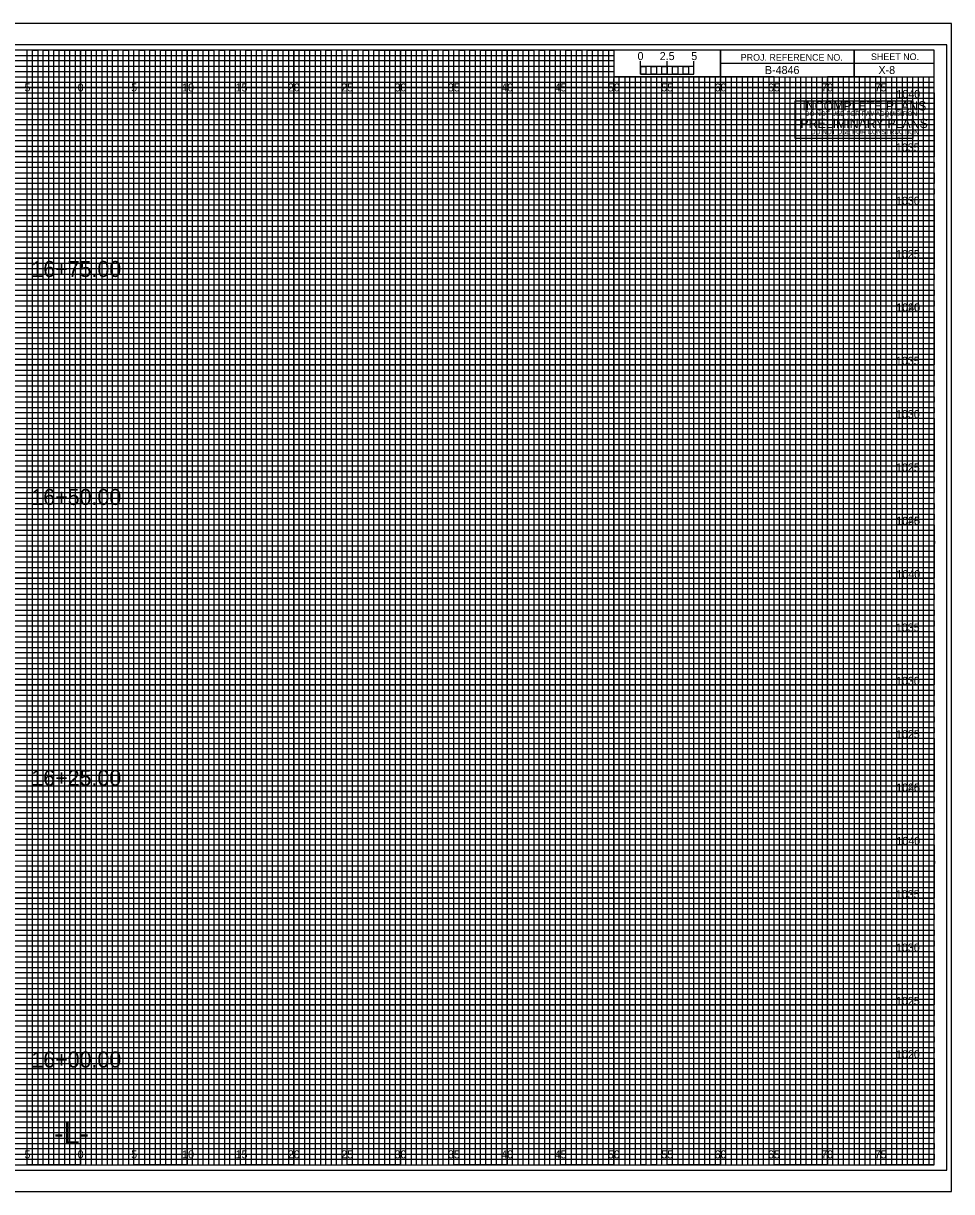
# Model space of a CAD drawing. Extents: x -7 to 162, y -2 to 987.
# Drawn here: x 74.6 to 161.7, y 767.5 to 877 of the extents above; entities that cross this region are included whole.
import ezdxf

# ---------------------------------------------------------------- set-up
doc = ezdxf.new("R2010")
doc.units = 0
for name, color, linetype in [('Default', 7, 'Continuous'), ('Exist Cross Section Cell', 7, 'Continuous'), ('Exist XS Center Line Elevation Label', 7, 'Continuous'), ('Exist XS Ground Line', 7, 'Continuous'), ('Prop CMT Concrete Structures', 7, 'Continuous'), ('Prop CMT DNC', 7, 'Continuous'), ('Prop CMT Guardrail Graphics', 7, 'Continuous'), ('Prop CMT Guardrail Widen Shoulder', 7, 'Continuous'), ('Prop CMT Pvmt Course 1', 7, 'Continuous'), ('Prop CMT Pvmt Surface', 7, 'Continuous'), ('Prop CMT Pvmt Surface Shoulder', 7, 'Continuous'), ('Prop CMT Shld Paved Course 1', 7, 'Continuous'), ('Prop CMT Shoulder Point', 7, 'Continuous'), ('Prop CMT Slope Grass', 7, 'Continuous'), ('Prop CMT Subgrade Earthwork', 7, 'Continuous'), ('Prop XS SE Text', 7, 'Continuous'), ('Prop XS Side Slope Text', 7, 'Continuous'), ('Typical Text Label CELL', 7, 'Continuous')]:
    doc.layers.add(name, color=color, linetype=linetype)

msp = doc.modelspace()

# ---------------------------------------------------------------- linework, layer by layer
at = {"layer": 'Default'}
for points in [[(146.99, 867.97), (146.99, 869.73), (158.01, 869.73), (158.01, 867.97)], [(146.99, 866.2), (146.99, 867.97), (158.01, 867.97), (158.01, 866.2)]]:
    msp.add_lwpolyline(points, close=True, dxfattribs=at)
at = {"layer": 'Exist XS Center Line Elevation Label'}
for points in [[(72.5, 770), (77.5, 770), (77.5, 874.5), (82.5, 874.5), (82.5, 770), (87.5, 770), (87.5, 874.5), (92.5, 874.5), (92.5, 770), (97.5, 770), (97.5, 874.5), (102.5, 874.5), (102.5, 770), (107.5, 770), (107.5, 874.5), (112.5, 874.5), (112.5, 770), (117.5, 770), (117.5, 874.5), (122.5, 874.5), (122.5, 770), (127.5, 770), (127.5, 874.5), (129.97, 874.5), (130, 874.5), (130, 872), (132.5, 872), (132.5, 770), (137.5, 770), (137.5, 872), (142.5, 872), (142.5, 770), (147.5, 770), (147.5, 872), (152.5, 872), (152.5, 770), (157.5, 770), (157.5, 872)], [(0, 872), (137.5, 872)], [(0, 862.5), (160, 862.5), (160, 867.5), (0, 867.5)], [(0, 852.5), (160, 852.5), (160, 857.5), (0, 857.5)], [(0, 842.5), (160, 842.5), (160, 847.5), (0, 847.5)], [(0, 832.5), (160, 832.5), (160, 837.5), (0, 837.5)], [(0, 822.5), (160, 822.5), (160, 827.5), (0, 827.5)], [(0, 812.5), (160, 812.5), (160, 817.5), (0, 817.5)], [(0, 802.5), (160, 802.5), (160, 807.5), (0, 807.5)], [(0, 792.5), (160, 792.5), (160, 797.5), (0, 797.5)], [(0, 782.5), (160, 782.5), (160, 787.5), (0, 787.5)], [(0, 772.5), (160, 772.5), (160, 777.5), (0, 777.5)]]:
    msp.add_lwpolyline(points, dxfattribs=at)
at = {"layer": 'Exist XS Ground Line'}
for p, q in [((75, 874.5), (70, 874.5)), ((75, 770), (75, 874.5)), ((85, 874.5), (80, 874.5)), ((80, 874.5), (80, 770)), ((85, 770), (85, 874.5)), ((95, 874.5), (90, 874.5)), ((90, 874.5), (90, 770)), ((95, 770), (95, 874.5)), ((105, 874.5), (100, 874.5)), ((100, 874.5), (100, 770)), ((105, 770), (105, 874.5)), ((115, 874.5), (110, 874.5)), ((110, 874.5), (110, 770)), ((115, 770), (115, 874.5)), ((125, 874.5), (120, 874.5)), ((120, 874.5), (120, 770)), ((125, 770), (125, 874.5)), ((130, 874.5), (130, 770)), ((135, 770), (135, 872)), ((145, 872), (140, 872)), ((140, 872), (140, 770)), ((145, 770), (145, 872)), ((155, 872), (150, 872)), ((150, 872), (150, 770)), ((155, 770), (155, 872)), ((80, 770), (75, 770)), ((90, 770), (85, 770)), ((100, 770), (95, 770)), ((110, 770), (105, 770)), ((120, 770), (115, 770)), ((130, 770), (125, 770)), ((140, 770), (135, 770)), ((150, 770), (145, 770)), ((160, 770), (155, 770)), ((160, 770), (160, 770))]:
    msp.add_line(p, q, dxfattribs=at)
for points in [[(0, 870), (160, 870), (160, 865), (0, 865)], [(0, 860), (160, 860), (160, 855), (0, 855)], [(0, 850), (160, 850), (160, 845), (0, 845)], [(0, 840), (160, 840), (160, 835), (0, 835)], [(0, 830), (160, 830), (160, 825), (0, 825)], [(0, 820), (160, 820), (160, 815), (0, 815)], [(0, 810), (160, 810), (160, 805), (0, 805)], [(0, 800), (160, 800), (160, 795), (0, 795)], [(0, 790), (160, 790), (160, 785), (0, 785)], [(0, 780), (160, 780), (160, 775), (0, 775)]]:
    msp.add_lwpolyline(points, dxfattribs=at)
at = {"layer": 'Prop CMT Concrete Structures'}
for p, q in [((75, 770), (75, 874.5)), ((80, 770), (80, 874.5)), ((85, 770), (85, 874.5)), ((90, 770), (90, 874.5)), ((95, 770), (95, 874.5)), ((100, 770), (100, 874.5)), ((105, 770), (105, 874.5)), ((110, 770), (110, 874.5)), ((115, 770), (115, 874.5)), ((120, 770), (120, 874.5)), ((125, 770), (125, 874.5)), ((130, 770), (130, 871.84)), ((135, 770), (135, 871.84)), ((140, 770), (140, 871.84)), ((145, 770), (145, 871.84)), ((150, 770), (150, 871.84)), ((155, 770), (155, 871.84)), ((0, 870), (160, 870)), ((0, 865), (160, 865)), ((0, 860), (160, 860)), ((0, 855), (160, 855)), ((0, 850), (160, 850)), ((0, 845), (160, 845)), ((0, 840), (160, 840)), ((0, 835), (160, 835)), ((0, 830), (160, 830)), ((0, 825), (160, 825)), ((0, 820), (160, 820)), ((0, 815), (160, 815)), ((0, 810), (160, 810)), ((0, 805), (160, 805)), ((0, 800), (160, 800)), ((0, 795), (160, 795)), ((0, 790), (160, 790)), ((0, 785), (160, 785)), ((0, 780), (160, 780)), ((0, 775), (160, 775))]:
    msp.add_line(p, q, dxfattribs=at)
at = {"layer": 'Prop CMT Guardrail Widen Shoulder'}
for p, q in [((161.65, 877), (-6.7, 877)), ((-6.7, 767.5), (161.65, 767.5))]:
    msp.add_line(p, q, dxfattribs=at)
at = {"layer": 'Prop CMT Pvmt Course 1'}
msp.add_lwpolyline([(-6.7, 767.5), (161.65, 767.5), (161.65, 877), (-6.7, 877)], close=True, dxfattribs=at)
at = {"layer": 'Prop CMT Pvmt Surface'}
for p, q in [((133.5, 872), (133, 872)), ((133, 872), (133, 770)), ((133.5, 770), (133.5, 872)), ((134.5, 872), (134, 872)), ((134, 872), (134, 770)), ((134.5, 770), (134.5, 872)), ((133, 770), (132.5, 770)), ((134, 770), (133.5, 770))]:
    msp.add_line(p, q, dxfattribs=at)
for points in [[(75, 770), (75.5, 770), (75.5, 874.5), (76, 874.5), (76, 770)], [(76, 770), (76.5, 770), (76.5, 874.5), (77, 874.5), (77, 770)], [(77.5, 770), (78, 770), (78, 874.5), (78.5, 874.5), (78.5, 770)], [(78.5, 770), (79, 770), (79, 874.5), (79.5, 874.5), (79.5, 770)], [(80, 770), (80.5, 770), (80.5, 874.5), (81, 874.5), (81, 770)], [(81, 770), (81.5, 770), (81.5, 874.5), (82, 874.5), (82, 770)], [(82.5, 770), (83, 770), (83, 874.5), (83.5, 874.5), (83.5, 770)], [(83.5, 770), (84, 770), (84, 874.5), (84.5, 874.5), (84.5, 770)], [(85, 770), (85.5, 770), (85.5, 874.5), (86, 874.5), (86, 770)], [(86, 770), (86.5, 770), (86.5, 874.5), (87, 874.5), (87, 770)], [(87.5, 770), (88, 770), (88, 874.5), (88.5, 874.5), (88.5, 770)], [(88.5, 770), (89, 770), (89, 874.5), (89.5, 874.5), (89.5, 770)], [(90, 770), (90.5, 770), (90.5, 874.5), (91, 874.5), (91, 770)], [(91, 770), (91.5, 770), (91.5, 874.5), (92, 874.5), (92, 770)], [(92.5, 770), (93, 770), (93, 874.5), (93.5, 874.5), (93.5, 770)], [(93.5, 770), (94, 770), (94, 874.5), (94.5, 874.5), (94.5, 770)], [(95, 770), (95.5, 770), (95.5, 874.5), (96, 874.5), (96, 770)], [(96, 770), (96.5, 770), (96.5, 874.5), (97, 874.5), (97, 770)], [(97.5, 770), (98, 770), (98, 874.5), (98.5, 874.5), (98.5, 770)], [(98.5, 770), (99, 770), (99, 874.5), (99.5, 874.5), (99.5, 770)], [(100, 770), (100.5, 770), (100.5, 874.5), (101, 874.5), (101, 770)], [(101, 770), (101.5, 770), (101.5, 874.5), (102, 874.5), (102, 770)], [(102.5, 770), (103, 770), (103, 874.5), (103.5, 874.5), (103.5, 770)], [(103.5, 770), (104, 770), (104, 874.5), (104.5, 874.5), (104.5, 770)], [(105, 770), (105.5, 770), (105.5, 874.5), (106, 874.5), (106, 770)], [(106, 770), (106.5, 770), (106.5, 874.5), (107, 874.5), (107, 770)], [(107.5, 770), (108, 770), (108, 874.5), (108.5, 874.5), (108.5, 770)], [(108.5, 770), (109, 770), (109, 874.5), (109.5, 874.5), (109.5, 770)], [(110, 770), (110.5, 770), (110.5, 874.5), (111, 874.5), (111, 770)], [(111, 770), (111.5, 770), (111.5, 874.5), (112, 874.5), (112, 770)], [(112.5, 770), (113, 770), (113, 874.5), (113.5, 874.5), (113.5, 770)], [(113.5, 770), (114, 770), (114, 874.5), (114.5, 874.5), (114.5, 770)], [(115, 770), (115.5, 770), (115.5, 874.5), (116, 874.5), (116, 770)], [(116, 770), (116.5, 770), (116.5, 874.5), (117, 874.5), (117, 770)], [(117.5, 770), (118, 770), (118, 874.5), (118.5, 874.5), (118.5, 770)], [(118.5, 770), (119, 770), (119, 874.5), (119.5, 874.5), (119.5, 770)], [(120, 770), (120.5, 770), (120.5, 874.5), (121, 874.5), (121, 770)], [(121, 770), (121.5, 770), (121.5, 874.5), (122, 874.5), (122, 770)], [(122.5, 770), (123, 770), (123, 874.5), (123.5, 874.5), (123.5, 770)], [(123.5, 770), (124, 770), (124, 874.5), (124.5, 874.5), (124.5, 770)], [(125, 770), (125.5, 770), (125.5, 874.5), (126, 874.5), (126, 770)], [(126, 770), (126.5, 770), (126.5, 874.5), (127, 874.5), (127, 770)], [(127.5, 770), (128, 770), (128, 874.5), (128.5, 874.5), (128.5, 770)], [(128.5, 770), (129, 770), (129, 874.5), (129.5, 874.5), (129.5, 770)], [(130, 770), (130.5, 770), (130.5, 872), (131.01, 872), (131.01, 770)], [(131, 770), (131.5, 770), (131.5, 872), (132, 872), (132, 770)], [(135, 770), (135.49, 770), (135.49, 872), (136, 872), (136, 770)], [(136, 770), (136.5, 770), (136.5, 872), (137.03, 872), (137.03, 770)], [(137.5, 770), (138, 770), (138, 872), (138.5, 872), (138.5, 770)], [(138.5, 770), (139, 770), (139, 872), (139.5, 872), (139.5, 770)], [(140, 770), (140.5, 770), (140.5, 872), (141, 872), (141, 770)], [(141, 770), (141.5, 770), (141.5, 872), (142, 872), (142, 770)], [(142.5, 770), (143, 770), (143, 872), (143.5, 872), (143.5, 770)], [(143.5, 770), (144, 770), (144, 872), (144.5, 872), (144.5, 770)], [(145, 770), (145.5, 770), (145.5, 872), (146, 872), (146, 770)], [(146, 770), (146.5, 770), (146.5, 872), (147, 872), (147, 770)], [(147.5, 770), (148, 770), (148, 872), (148.5, 872), (148.5, 770)], [(148.5, 770), (149, 770), (149, 872), (149.5, 872), (149.5, 770)], [(150, 770), (150.5, 770), (150.5, 872), (151, 872), (151, 770)], [(151, 770), (151.5, 770), (151.5, 872), (152, 872), (152, 770)], [(152.5, 770), (153, 770), (153, 872), (153.5, 872), (153.5, 770)], [(153.5, 770), (154, 770), (154, 872), (154.5, 872), (154.5, 770)], [(155, 770), (155.5, 770), (155.5, 872), (156, 872), (156, 770)], [(156, 770), (156.5, 770), (156.5, 872), (157, 872), (157, 770)], [(157.5, 770), (158, 770), (158, 872), (158.5, 872), (158.5, 770)], [(158.5, 770), (159, 770), (159, 872), (159.5, 872), (159.5, 770)]]:
    msp.add_lwpolyline(points, dxfattribs=at)
at = {"layer": 'Prop CMT Pvmt Surface Shoulder'}
for p, q in [((132.5, 872.25), (132.5, 873.45)), ((132.5, 872.95), (132.5, 873.45)), ((135, 872.25), (135, 873.45)), ((137.5, 872.25), (137.5, 873.45)), ((137.5, 872.95), (137.5, 873.45))]:
    msp.add_line(p, q, dxfattribs=at)
for points in [[(137.5, 872.95), (132.5, 872.95), (132.5, 872.25), (137.5, 872.25)], [(132.5, 872.95), (133, 872.95), (133, 872.25), (132.5, 872.25)], [(133.5, 872.95), (134, 872.95), (134, 872.25), (133.5, 872.25)], [(134.5, 872.95), (135, 872.95), (135, 872.25), (134.5, 872.25)], [(135.5, 872.95), (136, 872.95), (136, 872.25), (135.5, 872.25)], [(136.5, 872.95), (137, 872.95), (137, 872.25), (136.5, 872.25)]]:
    msp.add_lwpolyline(points, close=True, dxfattribs=at)
at = {"layer": 'Prop CMT Shld Paved Course 1'}
for p, q in [((0, 874), (130, 874)), ((130, 874), (130, 873.49)), ((130, 873.49), (0, 873.49)), ((0, 873), (130, 873)), ((130, 873), (130, 872.45)), ((130, 872.45), (0, 872.45)), ((0, 871.5), (160, 871.5))]:
    msp.add_line(p, q, dxfattribs=at)
for points in [[(0, 871), (135, 871), (160, 871), (160, 871), (0, 871)], [(0, 870.5), (160, 870.5), (160, 869.5), (0, 869.5)], [(0, 869), (160, 869), (160, 868.5), (0, 868.49)], [(0, 868), (160, 868), (160, 867), (0, 867)], [(0, 866.5), (160, 866.5), (160, 866), (0, 866)], [(0, 865.5), (160, 865.5), (160, 864.5), (0, 864.5)], [(0, 864), (160, 864), (160, 863.5), (0, 863.5)], [(0, 863), (160, 863), (160, 862), (0, 862)], [(0, 861.5), (160, 861.5), (160, 861), (0, 861)], [(0, 860.5), (160, 860.5), (160, 859.5), (0, 859.5)], [(0, 859), (160, 859), (160, 858.5), (0, 858.5)], [(0, 858), (160, 858), (160, 856.98), (160, 856.5), (160, 856), (0, 856)], [(0, 857), (160, 857), (160, 856.5), (0, 856.5)], [(0, 855.5), (160, 855.5), (160, 854.5), (0, 854.51)], [(0, 854.51), (160, 854.5), (160, 854), (0, 854)], [(0, 853.5), (160, 853.5), (160, 853), (0, 853)], [(0, 852), (160, 852), (160, 851.5), (0, 851.5)], [(0, 851), (160, 851), (160, 850.5), (0, 850.5)], [(-0.04, 849.45), (160, 849.45), (160, 848.94), (-0.04, 848.94)], [(0, 848.5), (160, 848.5), (160, 848), (0, 848)], [(0, 847), (160, 847), (160, 846.5), (0, 846.5)], [(0, 846), (160, 846), (160, 845.5), (0, 845.5)], [(0, 844.5), (160, 844.5), (160, 844), (0, 844)], [(0, 843.5), (160, 843.5), (160, 843), (0, 843)], [(0, 842), (160, 842), (160, 841.5), (0, 841.5)], [(0, 841), (160, 841), (160, 840.5), (0, 840.5)], [(0, 839.5), (160, 839.5), (160, 838.99), (0, 839)], [(0, 838.5), (160, 838.5), (160, 838), (0, 838)], [(0, 837), (160, 837), (160, 836.5), (0, 836.5)], [(0, 836), (160, 836), (160, 835.5), (0, 835.5)], [(0, 834.5), (160, 834.5), (160, 834), (0, 834)], [(0, 833.5), (160, 833.5), (160, 833), (0, 833)], [(0, 832), (160, 832), (160, 831.5), (0, 831.5)], [(0, 831), (160, 831), (160, 830.5), (0, 830.5)], [(0, 829.5), (160, 829.5), (160, 829), (0, 829)], [(0, 828.5), (160.03, 828.46), (160, 828), (0, 828)], [(0, 827), (160, 827), (160, 826.5), (0, 826.5)], [(0, 826), (160, 826), (160, 825.5), (0, 825.5)], [(0, 824.5), (160, 824.5), (160, 824), (0, 824)], [(0, 823.5), (160, 823.5), (160, 823), (0, 823)], [(0, 822), (160, 822), (160, 821.5), (0, 821.5)], [(0, 821), (160, 821), (160, 820.5), (0, 820.5)], [(0, 819.5), (160, 819.5), (160, 819), (0, 819)], [(0, 818.5), (160, 818.5), (160, 818), (0, 818)], [(0, 817), (160, 817), (160, 816.5), (0, 816.5)], [(0, 816), (160, 816), (160, 815.5), (0, 815.5)], [(0, 814.5), (160, 814.5), (160, 814), (0, 814)], [(0, 813.5), (160, 813.5), (160, 813), (0, 813)], [(0, 812), (160, 812), (160, 811.5), (0, 811.5)], [(0, 811), (160, 811), (160, 810.5), (0, 810.5)], [(0, 809.5), (160, 809.5), (160, 808.99), (0, 809)], [(0, 808.5), (160, 808.5), (160, 808), (0, 808)], [(0, 807), (160, 807), (160, 806.5), (0, 806.5)], [(0, 806), (160, 806), (160, 805.5), (0, 805.5)], [(0, 804.5), (160, 804.5), (160, 804), (0, 804)], [(0, 803.5), (160, 803.5), (160, 803), (0, 803)], [(0, 802), (160, 802), (160, 801.5), (0, 801.5)], [(0, 801), (160, 801), (160, 800.5), (0, 800.5)], [(0, 799.5), (160, 799.5), (160, 799), (0, 799)], [(0, 798.5), (160.03, 798.46), (160, 798), (0, 798)], [(0, 797), (160, 797), (160, 796.5), (0, 796.5)], [(0, 796), (160, 796), (160, 795.5), (0, 795.5)], [(0, 794.5), (160, 794.5), (160, 794), (0, 794)], [(0, 793.5), (160, 793.5), (160, 793), (0, 793)], [(0, 792), (160, 792), (160, 791.5), (0, 791.5)], [(0, 791), (160, 791), (160, 790.5), (0, 790.5)], [(0, 789.5), (160, 789.5), (160, 789), (0, 789)], [(0, 788.5), (160, 788.5), (160, 788), (0, 788)], [(0, 787), (160, 787), (160, 786.5), (0, 786.5)], [(0, 786), (160, 786), (160, 785.5), (0, 785.5)], [(0, 784.5), (160, 784.5), (160, 784), (0, 784)], [(0, 783.5), (160, 783.5), (160, 783), (0, 783)], [(0, 782), (160, 782), (160, 781.5), (0, 781.5)], [(0, 781), (160, 781), (160, 780.5), (0, 780.5)], [(0, 779.5), (160, 779.5), (160, 779), (0, 779)], [(0, 778.5), (160, 778.5), (160, 778), (0, 778)], [(0, 777), (160, 777), (160, 776.5), (0, 776.5)], [(0, 776), (160, 776), (160, 775.5), (0, 775.5)], [(0, 774.5), (160, 774.5), (160, 774), (0, 774)], [(0, 773.5), (160, 773.5), (160, 773), (0, 773)], [(0, 772), (160, 772), (160, 771.5), (0, 771.5)], [(0, 771), (160, 771), (160, 770.5), (0, 770.5)]]:
    msp.add_lwpolyline(points, dxfattribs=at)
at = {"layer": 'Prop CMT Slope Grass'}
msp.add_lwpolyline([(-5.4, 769.5), (161.2, 769.5), (161.2, 875), (-5.4, 875)], close=True, dxfattribs=at)
at = {"layer": 'Prop CMT Subgrade Earthwork'}
for p, q in [((152.5, 874.5), (152.5, 872)), ((152.5, 872), (152.5, 874.5)), ((160, 873.25), (140, 873.25)), ((140, 873.25), (140, 872)), ((140, 872), (160, 872))]:
    msp.add_line(p, q, dxfattribs=at)
for points in [[(160, 874.5), (0, 874.5), (0, 770), (160, 770)], [(140, 874.5), (130, 874.5), (130, 872.01), (140, 872.01)], [(160, 874.5), (140, 874.5), (140, 872), (160, 872)]]:
    msp.add_lwpolyline(points, close=True, dxfattribs=at)

# ---------------------------------------------------------------- texts
at = {"layer": 'Default'}
for s, height, p in [('INCOMPLETE PLANS', 0.864, (147.66, 868.84)), ('DO NOT USE FOR R/W ACQUISITION', 0.432, (147.9, 868.32)), ('PRELIMINARY PLANS', 0.864, (147.47, 867.19)), ('DO NOT USE FOR CONSTRUCTION', 0.432, (148.46, 866.61))]:
    msp.add_text(s, height=height, dxfattribs=at).set_placement(p)
at = {"layer": 'Exist Cross Section Cell'}
for s, p in [('5', (74.74, 870.62)), ('0', (79.73, 870.62)), ('0', (79.73, 870.62)), ('5', (84.74, 870.62)), ('10', (89.52, 870.62)), ('15', (94.53, 870.62)), ('20', (99.43, 870.62)), ('25', (104.44, 870.62)), ('30', (109.43, 870.62)), ('35', (114.44, 870.62)), ('40', (119.43, 870.62)), ('45', (124.44, 870.62)), ('50', (129.43, 870.62)), ('55', (134.44, 870.62)), ('60', (139.43, 870.62)), ('65', (144.44, 870.62)), ('70', (149.43, 870.62)), ('75', (154.44, 870.62)), ('5', (74.74, 770.62)), ('0', (79.73, 770.62)), ('0', (79.73, 770.62)), ('5', (84.74, 770.62)), ('10', (89.52, 770.62)), ('15', (94.53, 770.62)), ('20', (99.43, 770.62)), ('25', (104.44, 770.62)), ('30', (109.43, 770.62)), ('35', (114.44, 770.62)), ('40', (119.43, 770.62)), ('45', (124.44, 770.62)), ('50', (129.43, 770.62)), ('55', (134.44, 770.62)), ('60', (139.43, 770.62)), ('65', (144.44, 770.62)), ('70', (149.43, 770.62)), ('75', (154.44, 770.62))]:
    msp.add_text(s, height=0.75, dxfattribs=at).set_placement(p)
at = {"layer": 'Prop CMT DNC'}
msp.add_text('-L-', height=2, dxfattribs=at).set_placement((77.53, 772))
at = {"layer": 'Prop CMT Guardrail Graphics'}
msp.add_text('B-4846', height=0.75, dxfattribs=at).set_placement((144.15, 872.25))
at = {"layer": 'Prop CMT Pvmt Surface Shoulder'}
msp.add_text('0', height=0.75, dxfattribs=at).set_placement((132.21, 873.56))
at = {"layer": 'Prop CMT Shoulder Point'}
for s, p in [('2.5', (134.29, 873.56)), ('5', (137.24, 873.56))]:
    msp.add_text(s, height=0.75, dxfattribs=at).set_placement(p)
at = {"layer": 'Prop CMT Subgrade Earthwork'}
for s, p in [('PROJ. REFERENCE NO.', (141.88, 873.5)), ('SHEET NO.', (154.09, 873.56))]:
    msp.add_text(s, height=0.625, dxfattribs=at).set_placement(p)
at = {"layer": 'Prop XS SE Text'}
msp.add_text('X-8', height=0.75, dxfattribs=at).set_placement((154.79, 872.25))
at = {"layer": 'Prop XS Side Slope Text'}
for s, p in [('16+75.00', (75.39, 853.23)), ('16+50.00', (75.39, 831.86)), ('16+25.00', (75.39, 805.54)), ('16+00.00', (75.39, 779.13))]:
    msp.add_text(s, height=1.5, dxfattribs=at).set_placement(p)
at = {"layer": 'Typical Text Label CELL'}
for s, p in [('1040', (156.47, 870)), ('1035', (156.42, 865)), ('1030', (156.43, 860)), ('1025', (156.43, 855)), ('1020', (156.44, 850)), ('1040', (156.47, 850)), ('1035', (156.42, 845)), ('1030', (156.43, 840)), ('1025', (156.43, 835)), ('1020', (156.44, 830)), ('1045', (156.46, 830)), ('1040', (156.47, 825)), ('1035', (156.42, 820)), ('1030', (156.43, 815)), ('1025', (156.43, 810)), ('1020', (156.44, 805)), ('1045', (156.46, 805)), ('1040', (156.47, 800)), ('1035', (156.42, 795)), ('1030', (156.43, 790)), ('1025', (156.43, 785)), ('1020', (156.44, 780))]:
    msp.add_text(s, height=0.75, dxfattribs=at).set_placement(p)

doc.saveas('drawing.dxf')
